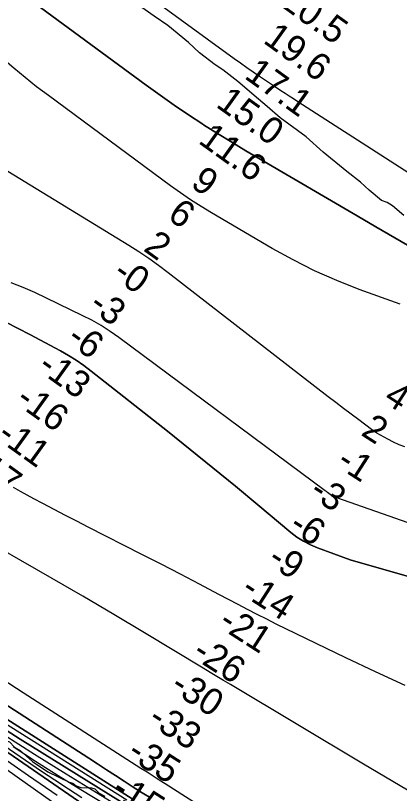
# Model space of a CAD drawing. Extents: x 3161615 to 3199515, y 867541 to 892976.
# Drawn here: x 3185169 to 3186134, y 880499 to 882454 of the extents above; entities that cross this region are included whole.
import ezdxf

# ---------------------------------------------------------------- set-up
doc = ezdxf.new("R2010")
doc.units = 0
for name, color, linetype in [('V-RIVR-EDGE', 7, 'Continuous'), ('V-RIVR-RANG', 7, 'Continuous'), ('V-TOPO-DPTH', 7, 'Continuous'), ('V-TOPO-MINR', 7, 'Continuous'), ('V-TOPO-WATR', 7, 'Continuous')]:
    doc.layers.add(name, color=color, linetype=linetype)

msp = doc.modelspace()

# ---------------------------------------------------------------- linework, layer by layer
at = {"layer": 'V-RIVR-EDGE'}
for points in [[(3185780, 882244), (3185727.6, 882288), (3185689.8, 882317.2), (3185671.2, 882329.9), (3185631.2, 882360.4), (3185603.5, 882386.5), (3185551.9, 882429.3), (3185517.6, 882452.4), (3185464.2, 882489.9)], [(3186144.9, 881951.8), (3186117.1, 881975.4), (3186103.2, 881984.5), (3186088.9, 881988.9), (3186058.1, 882015.1), (3186036, 882035.1), (3186001.7, 882062.2), (3185942.7, 882111), (3185899.8, 882149.3), (3185834.3, 882196.9), (3185801.7, 882225.7), (3185780, 882244)], [(3185123.6, 880650.5), (3185136.9, 880634.7), (3185154, 880628.5), (3185166.4, 880615.1), (3185180.2, 880607.4), (3185211.6, 880579.7), (3185250.2, 880553.4), (3185304, 880527.5), (3185312.6, 880525.1), (3185321.1, 880517.9), (3185333, 880514.1), (3185360.2, 880513.1), (3185368.3, 880510.7), (3185378.8, 880499.7), (3185393.6, 880492)]]:
    msp.add_lwpolyline(points, dxfattribs=at)
at = {"layer": 'V-TOPO-DPTH'}
for points in [[(3185190.7, 882504.9), (3185497.7, 882278.7), (3185532.6, 882253.5), (3185567.8, 882228.8), (3185603.5, 882204.8), (3185639.6, 882181.3), (3185641.9, 882179.7), (3185677.1, 882157.5), (3185712.5, 882135.6), (3185748.2, 882114.1), (3185784, 882092.8), (3186028, 881950.3), (3186075.3, 881922.7), (3186122.7, 881895.2), (3186170.1, 881867.9)], [(3185190.7, 882504.9), (3185497.7, 882278.7), (3185532.6, 882253.5), (3185567.8, 882228.8), (3185603.5, 882204.8), (3185639.6, 882181.3), (3185641.9, 882179.7), (3185677.1, 882157.5), (3185712.5, 882135.6), (3185748.2, 882114.1), (3185784, 882092.8), (3186028, 881950.3), (3186075.3, 881922.7), (3186122.7, 881895.2), (3186170.1, 881867.9)], [(3186148.1, 881369.8), (3186133.5, 881375.3), (3186119.3, 881381.8), (3186105.4, 881389.1), (3186077.2, 881404.9), (3186073.8, 881406.9), (3186070.4, 881409.1), (3186067.1, 881411.3), (3186063.9, 881413.6), (3186031.8, 881437.7), (3186012.6, 881452.2), (3185993.5, 881466.7), (3185974.4, 881481.4), (3185955.3, 881496), (3185552.4, 881807.8), (3185528.4, 881825.8), (3185504, 881843.2), (3185479, 881859.8), (3185453.7, 881875.9), (3185134.8, 882071.1)], [(3186148.1, 881369.8), (3186133.5, 881375.3), (3186119.3, 881381.8), (3186105.4, 881389.1), (3186077.2, 881404.9), (3186073.8, 881406.9), (3186070.4, 881409.1), (3186067.1, 881411.3), (3186063.9, 881413.6), (3186031.8, 881437.7), (3186012.6, 881452.2), (3185993.5, 881466.7), (3185974.4, 881481.4), (3185955.3, 881496), (3185552.4, 881807.8), (3185528.4, 881825.8), (3185504, 881843.2), (3185479, 881859.8), (3185453.7, 881875.9), (3185134.8, 882071.1)], [(3185146, 881682.4), (3185204.7, 881652.3), (3185281.7, 881611.3), (3185301.9, 881599.8), (3185321.7, 881587.7), (3185340.8, 881574.4), (3185359.4, 881560.5), (3185550.6, 881409.5), (3185608, 881363.7), (3185665.2, 881317.6), (3185722, 881271), (3185778.5, 881224.1), (3185860.8, 881155.2), (3185876.5, 881143.4), (3185892.8, 881132.8), (3185910.2, 881123.9), (3185928.2, 881116.2), (3186010.5, 881085.9), (3186458.2, 880958.1)], [(3186458.2, 880958.1), (3186010.5, 881085.9), (3185928.2, 881116.2), (3185910.2, 881123.9), (3185892.8, 881132.8), (3185876.5, 881143.4), (3185860.8, 881155.2), (3185778.5, 881224.1), (3185722, 881271), (3185665.2, 881317.6), (3185608, 881363.7), (3185550.6, 881409.5), (3185359.4, 881560.5), (3185340.8, 881574.4), (3185321.7, 881587.7), (3185301.9, 881599.8), (3185281.7, 881611.3), (3185204.7, 881652.3), (3185146, 881682.4)], [(3185163.2, 881268.9), (3185180.1, 881259), (3185197.2, 881249.5), (3185214.4, 881240.2), (3185236.7, 881228.6), (3185265.3, 881213.7), (3185293.8, 881198.9), (3185322.4, 881184.2), (3185351, 881169.5), (3185485.8, 881100.6), (3185534.2, 881075.8), (3185582.6, 881050.8), (3185630.8, 881025.6), (3185679, 881000.2), (3185727.5, 880974.6), (3185751.4, 880962.1), (3185775.5, 880949.7), (3185799.6, 880937.6), (3185823.8, 880925.7), (3185923.8, 880876.9), (3185998.3, 880841.1), (3186073, 880805.7), (3186148, 880771)], [(3185163.2, 881268.9), (3185180.1, 881259), (3185197.2, 881249.5), (3185214.4, 881240.2), (3185236.7, 881228.6), (3185265.3, 881213.7), (3185293.8, 881198.9), (3185322.4, 881184.2), (3185351, 881169.5), (3185485.8, 881100.6), (3185534.2, 881075.8), (3185582.6, 881050.8), (3185630.8, 881025.6), (3185679, 881000.2), (3185727.5, 880974.6), (3185751.4, 880962.1), (3185775.5, 880949.7), (3185799.6, 880937.6), (3185823.8, 880925.7), (3185923.8, 880876.9), (3185998.3, 880841.1), (3186073, 880805.7), (3186148, 880771)], [(3186154.2, 880507.7), (3186117.4, 880529.3), (3186080.7, 880551.1), (3186044, 880572.9), (3185709.1, 880772.7), (3185692, 880782.9), (3185674.9, 880793.1), (3185657.9, 880803.3), (3185640.9, 880813.6), (3185493.3, 880902.6), (3185416.1, 880948.8), (3185338.5, 880994.6), (3185260.6, 881039.7), (3185182.5, 881084.4), (3185082.1, 881141.4)], [(3186154.2, 880507.7), (3186117.4, 880529.3), (3186080.7, 880551.1), (3186044, 880572.9), (3185709.1, 880772.7), (3185692, 880782.9), (3185674.9, 880793.1), (3185657.9, 880803.3), (3185640.9, 880813.6), (3185493.3, 880902.6), (3185416.1, 880948.8), (3185338.5, 880994.6), (3185260.6, 881039.7), (3185182.5, 881084.4), (3185082.1, 881141.4)], [(3184909.8, 880873.8), (3185352.8, 880587.6), (3185375.2, 880573.2), (3185397.6, 880558.7), (3185420, 880544.2), (3185442.4, 880529.7), (3185464.9, 880515.3), (3185487.5, 880501.1), (3185510.2, 880487.2)], [(3185510.2, 880487.2), (3185487.5, 880501.1), (3185464.9, 880515.3), (3185442.4, 880529.7), (3185420, 880544.2), (3185397.6, 880558.7), (3185375.2, 880573.2), (3185352.8, 880587.6), (3184909.8, 880873.8)], [(3185462.3, 880485.9), (3184939.5, 880817.7)], [(3185462.3, 880485.9), (3184939.5, 880817.7)], [(3185364.6, 880453.9), (3184847.1, 880809.4)], [(3185135.2, 880786.9), (3185188.1, 880753.1), (3185484.2, 880563.1), (3185499.5, 880553.3), (3185514.7, 880543.6), (3185530, 880533.8), (3185545.3, 880524.1), (3186047.6, 880203.3)], [(3185135.2, 880786.9), (3185188.1, 880753.1), (3185484.2, 880563.1), (3185499.5, 880553.3), (3185514.7, 880543.6), (3185530, 880533.8), (3185545.3, 880524.1), (3186047.6, 880203.3)], [(3185118.8, 880674.9), (3185180.6, 880635.9), (3185433, 880479.2)], [(3185433, 880479.2), (3185180.6, 880635.9), (3185118.8, 880674.9)], [(3185162.7, 880617.4), (3185218.9, 880580.5), (3185275.7, 880544.5), (3185332.9, 880509.2), (3185396.5, 880470.5)], [(3185162.7, 880617.4), (3185218.9, 880580.5), (3185275.7, 880544.5), (3185332.9, 880509.2), (3185396.5, 880470.5)]]:
    msp.add_lwpolyline(points, dxfattribs=at)
at = {"layer": 'V-TOPO-MINR'}
for points in [[(3186135.7, 881728.3), (3186124.3, 881732.5), (3186032.9, 881765.8), (3185976.5, 881788.1), (3185921, 881812.4), (3185866.9, 881839.7), (3185813.8, 881868.9), (3185661.8, 881957.9), (3185635.3, 881974), (3185609.1, 881990.7), (3185583.5, 882008.2), (3185558.2, 882026.2), (3185251.4, 882252.7), (3185221.9, 882275.1), (3185192.8, 882298), (3185164.3, 882321.6), (3185136.2, 882345.7), (3185132.5, 882349), (3185106.8, 882372.1), (3185081.5, 882395.5), (3185056.5, 882419.4), (3185031.9, 882443.7), (3184632.3, 882844.3)], [(3186378.1, 881916), (3185878.5, 882237.5), (3185867.9, 882244.3), (3185857.3, 882251.2), (3185846.7, 882258.2), (3185836.1, 882265.1), (3185820.1, 882275.6), (3185817.6, 882277.3), (3185815, 882279), (3185812.4, 882280.8), (3185809.8, 882282.5), (3185782.6, 882300.7), (3185766.5, 882311.7), (3185750.4, 882322.8), (3185734.5, 882334.1), (3185718.7, 882345.4), (3185320.8, 882635.6)], [(3186148.1, 881369.8), (3186133.5, 881375.3), (3186119.3, 881381.8), (3186105.4, 881389.1), (3186077.2, 881404.9), (3186073.8, 881406.9), (3186070.4, 881409.1), (3186067.1, 881411.3), (3186063.9, 881413.6), (3186031.8, 881437.7), (3186012.6, 881452.2), (3185993.5, 881466.7), (3185974.4, 881481.4), (3185955.3, 881496), (3185552.4, 881807.8), (3185528.4, 881825.8), (3185504, 881843.2), (3185479, 881859.8), (3185453.7, 881875.9), (3185134.8, 882071.1)], [(3186173.1, 881173.4), (3185976.8, 881242.4), (3185975.8, 881242.7), (3185971.6, 881244.1), (3185968.5, 881245.2), (3185965.4, 881246.6), (3185964.9, 881247), (3185959.8, 881250.8), (3185956.7, 881253.1), (3185953.7, 881255.3), (3185950.6, 881257.6), (3185947.6, 881259.9), (3185429, 881644.7), (3185406.8, 881660.2), (3185384.1, 881674.9), (3185360.5, 881688.2), (3185336.5, 881700.6), (3185217.5, 881757.7), (3185188, 881770.7), (3185158.1, 881782.6)], [(3186458.2, 880958.1), (3186010.5, 881085.9), (3185928.2, 881116.2), (3185910.2, 881123.9), (3185892.8, 881132.8), (3185876.5, 881143.4), (3185860.8, 881155.2), (3185778.5, 881224.1), (3185722, 881271), (3185665.2, 881317.6), (3185608, 881363.7), (3185550.6, 881409.5), (3185359.4, 881560.5), (3185340.8, 881574.4), (3185321.7, 881587.7), (3185301.9, 881599.8), (3185281.7, 881611.3), (3185204.7, 881652.3), (3185146, 881682.4)], [(3185163.2, 881268.9), (3185180.1, 881259), (3185197.2, 881249.5), (3185214.4, 881240.2), (3185236.7, 881228.6), (3185265.3, 881213.7), (3185293.8, 881198.9), (3185322.4, 881184.2), (3185351, 881169.5), (3185485.8, 881100.6), (3185534.2, 881075.8), (3185582.6, 881050.8), (3185630.8, 881025.6), (3185679, 881000.2), (3185727.5, 880974.6), (3185751.4, 880962.1), (3185775.5, 880949.7), (3185799.6, 880937.6), (3185823.8, 880925.7), (3185923.8, 880876.9), (3185998.3, 880841.1), (3186073, 880805.7), (3186148, 880771)], [(3186154.2, 880507.7), (3186117.4, 880529.3), (3186080.7, 880551.1), (3186044, 880572.9), (3185709.1, 880772.7), (3185692, 880782.9), (3185674.9, 880793.1), (3185657.9, 880803.3), (3185640.9, 880813.6), (3185493.3, 880902.6), (3185416.1, 880948.8), (3185338.5, 880994.6), (3185260.6, 881039.7), (3185182.5, 881084.4), (3185082.1, 881141.4)], [(3185510.2, 880487.2), (3185487.5, 880501.1), (3185464.9, 880515.3), (3185442.4, 880529.7), (3185420, 880544.2), (3185397.6, 880558.7), (3185375.2, 880573.2), (3185352.8, 880587.6), (3184909.8, 880873.8)], [(3184844.8, 880822.6), (3185234.4, 880555.5), (3185267.9, 880533), (3185301.7, 880510.8), (3185335.9, 880489.3)], [(3184939.5, 880817.7), (3185462.3, 880485.9)], [(3184847.1, 880809.4), (3185364.6, 880453.9)], [(3185135.2, 880786.9), (3185188.1, 880753.1), (3185484.2, 880563.1), (3185499.5, 880553.3), (3185514.7, 880543.6), (3185530, 880533.8), (3185545.3, 880524.1), (3186047.6, 880203.3)], [(3184869.6, 880755.5), (3185377.4, 880396.2)], [(3185058.8, 880727.5), (3185448.5, 880482.8)], [(3185118.8, 880674.9), (3185180.6, 880635.9), (3185433, 880479.2)], [(3185137.6, 880648.5), (3185216.5, 880598.3), (3185295.8, 880548.8), (3185415.7, 880475.1)], [(3185128.6, 880594.8), (3185201.2, 880544.7), (3185273.8, 880494.7)]]:
    msp.add_lwpolyline(points, dxfattribs=at)
at = {"layer": 'V-TOPO-WATR'}
for points in [[(3186170.1, 881867.9), (3186122.7, 881895.2), (3186075.3, 881922.7), (3186028, 881950.3), (3185784, 882092.8), (3185748.2, 882114.1), (3185712.5, 882135.6), (3185677.1, 882157.5), (3185641.9, 882179.7), (3185639.6, 882181.3), (3185603.5, 882204.8), (3185567.8, 882228.8), (3185532.6, 882253.5), (3185497.7, 882278.7), (3185190.7, 882504.9)], [(3185162.7, 880617.4), (3185218.9, 880580.5), (3185275.7, 880544.5), (3185332.9, 880509.2), (3185396.5, 880470.5)]]:
    msp.add_lwpolyline(points, dxfattribs=at)

# ---------------------------------------------------------------- texts
at = {"layer": 'V-RIVR-RANG'}
for s, rotation, p in [('20.5', 324.305, (3185831, 882480.2)), ('19.6', 324.305, (3185788.8, 882387.4)), ('17.1', 324.305, (3185741.6, 882298.1)), ('15.0', 324.305, (3185670.2, 882226.3)), ('11.6', 324.305, (3185625.7, 882135.2)), ('9', 324.305, (3185606.3, 882025.9)), ('6', 324.305, (3185548, 881944.7)), ('2', 324.305, (3185487.8, 881864.8)), ('-0', 324.305, (3185409.8, 881797.7)), ('-3', 324.305, (3185349.8, 881717.7)), ('-6', 324.305, (3185294.3, 881634.5)), ('-13', 324.305, (3185221.2, 881563.8)), ('4', 327.2908, (3186091.4, 881483.8)), ('-16', 324.305, (3185165.7, 881480.6)), ('2', 327.2908, (3186034.9, 881401.2)), ('-11', 324.305, (3185118.9, 881391)), ('-17', 324.305, (3185047.4, 881319.3)), ('-1', 327.2908, (3185972.7, 881322.3)), ('-3', 327.2908, (3185904.3, 881247.4)), ('-6', 327.2908, (3185852.9, 881161.6)), ('-9', 327.2908, (3185799.1, 881077.3)), ('-14', 327.2908, (3185732.2, 881001.4)), ('-21', 327.2908, (3185675.5, 880918.9)), ('-26', 327.2908, (3185609.7, 880842.4)), ('-30', 327.2908, (3185554.6, 880758.9)), ('-33', 327.2908, (3185498.5, 880676)), ('-35', 327.2908, (3185445.9, 880591)), ('-15', 327.2908, (3185406.5, 880497.5))]:
    msp.add_text(s, height=67, rotation=rotation, dxfattribs=at).set_placement(p)

doc.saveas('drawing.dxf')
